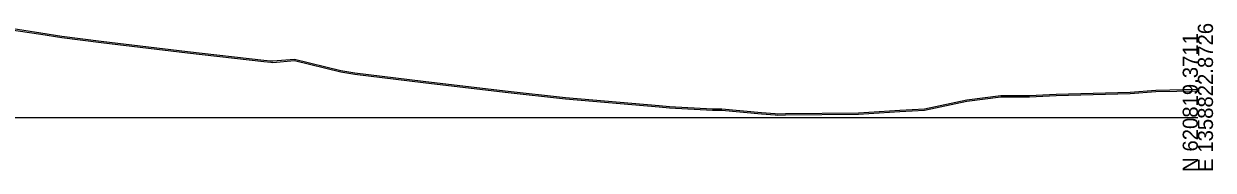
# Model space of a CAD drawing. Extents: x -26 to 803, y -27 to 3586.
# Drawn here: x 583.1 to 802.8, y 2490.3 to 2517.3 of the extents above; entities that cross this region are included whole.
import ezdxf

# ---------------------------------------------------------------- set-up
doc = ezdxf.new("R2010")
doc.units = 0
for name, color, linetype in [('DESIGN - SHEET - Light Grid', 7, 'Continuous'), ('SURVEY - GROUND - Bottom of Topsoil Layer', 7, 'Continuous'), ('SURVEY - GROUND - Top of Ground', 7, 'Continuous')]:
    doc.layers.add(name, color=color, linetype=linetype)

msp = doc.modelspace()

# ---------------------------------------------------------------- linework, layer by layer
at = {"layer": 'DESIGN - SHEET - Light Grid'}
msp.add_line((400, 2500), (800, 2500), dxfattribs=at)
at = {"layer": 'SURVEY - GROUND - Bottom of Topsoil Layer'}
for p, q in [((579.97, 2516.36), (586.26, 2515.41)), ((586.26, 2515.41), (590.16, 2514.8)), ((590.16, 2514.8), (597.41, 2513.87)), ((597.41, 2513.87), (613.34, 2511.97)), ((613.34, 2511.97), (627.48, 2510.36)), ((627.48, 2510.36), (628.73, 2510.23)), ((628.73, 2510.23), (629.13, 2510.21)), ((629.13, 2510.21), (633.11, 2510.53)), ((633.11, 2510.53), (641.7, 2508.43)), ((641.7, 2508.43), (644.28, 2508.02)), ((644.28, 2508.02), (656.91, 2506.46)), ((656.91, 2506.46), (672.07, 2504.71)), ((792.27, 2504.8), (800, 2504.98)), ((672.07, 2504.71), (683.18, 2503.48)), ((683.18, 2503.48), (700.49, 2501.99)), ((749.51, 2501.38), (757.3, 2503.07)), ((757.3, 2503.07), (763.61, 2503.83)), ((763.61, 2503.83), (768.9, 2503.87)), ((768.9, 2503.87), (773.82, 2504.08)), ((773.82, 2504.08), (787.52, 2504.46)), ((787.52, 2504.46), (792.27, 2504.8)), ((700.49, 2501.99), (702.41, 2501.81)), ((702.41, 2501.81), (710.36, 2501.36)), ((710.36, 2501.36), (712.07, 2501.36)), ((712.07, 2501.36), (719.41, 2500.72)), ((719.41, 2500.72), (721.94, 2500.51)), ((721.94, 2500.51), (722.33, 2500.48)), ((722.33, 2500.48), (723.83, 2500.5)), ((723.83, 2500.5), (737.33, 2500.65)), ((737.33, 2500.65), (744.93, 2501.11)), ((744.93, 2501.11), (749.51, 2501.38))]:
    msp.add_line(p, q, dxfattribs=at)
at = {"layer": 'SURVEY - GROUND - Top of Ground'}
msp.add_lwpolyline([(579.97, 2516.61), (586.26, 2515.66), (590.16, 2515.05), (597.41, 2514.12), (613.34, 2512.22), (627.48, 2510.61), (628.73, 2510.48), (629.13, 2510.46), (633.11, 2510.78), (641.7, 2508.68), (644.28, 2508.27), (656.91, 2506.71), (672.07, 2504.96), (683.18, 2503.73), (700.49, 2502.24), (702.41, 2502.06), (710.36, 2501.61), (712.07, 2501.61), (719.41, 2500.97), (721.94, 2500.76), (722.33, 2500.73), (723.83, 2500.75), (737.33, 2500.9), (744.93, 2501.36), (749.51, 2501.63), (757.3, 2503.32), (763.61, 2504.08), (768.9, 2504.12), (773.82, 2504.33), (787.52, 2504.71), (792.27, 2505.05), (800, 2505.23)], dxfattribs=at)

# ---------------------------------------------------------------- texts
at = {"layer": 'DESIGN - SHEET - Light Grid'}
for s, p in [('E 1358822.8726', (802.8, 2490)), ('N 620819.3711', (800, 2490))]:
    msp.add_text(s, height=2.8, rotation=90, dxfattribs=at).set_placement(p)

doc.saveas('drawing.dxf')
